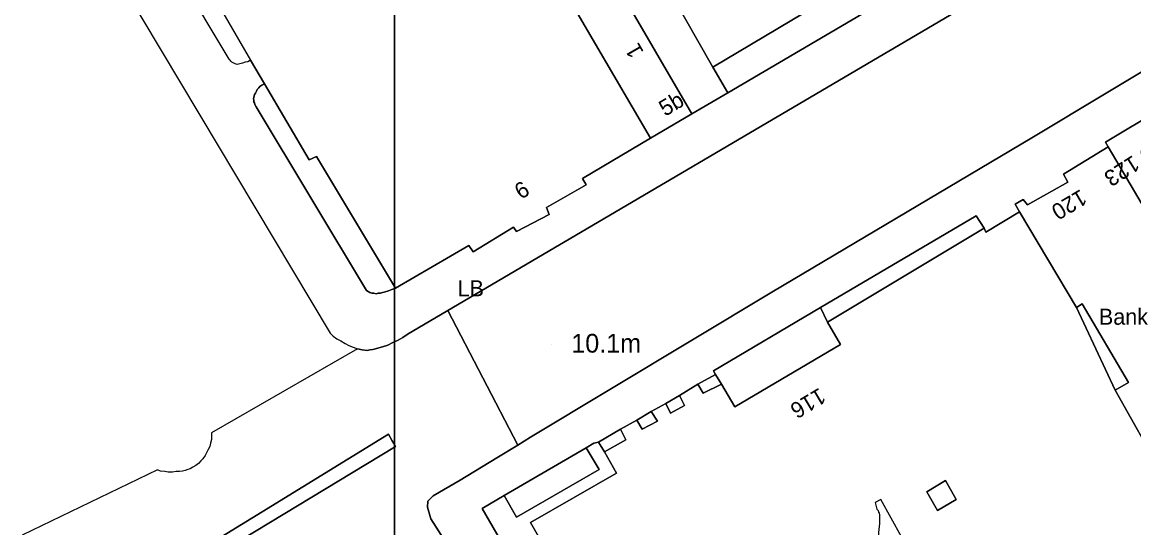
# Model space of a CAD drawing. Extents: x 529240 to 530363, y 179600 to 180767.
# Drawn here: x 529681.3 to 529784.9, y 180348 to 180395.2 of the extents above; entities that cross this region are included whole.
import ezdxf

# ---------------------------------------------------------------- set-up
doc = ezdxf.new("R2010")
doc.units = 0
for name, color, linetype in [('Building', 7, 'Continuous'), ('General surface', 7, 'Continuous'), ('Road Or Track', 7, 'Continuous'), ('Roadside', 7, 'Continuous'), ('Structure', 7, 'Continuous'), ('Unclassified', 7, 'Continuous')]:
    doc.layers.add(name, color=color, linetype=linetype)

msp = doc.modelspace()

# ---------------------------------------------------------------- linework, layer by layer
at = {"layer": 'Building'}
for points in [[(529747.1, 180388.6), (529784.75, 180410.75), (529775.55, 180427), (529778.6, 180428.75), (529776, 180433.1), (529773.05, 180431.45), (529759.35, 180455.35), (529756.45, 180453.55), (529769.05, 180432.45), (529767.7, 180431.65), (529772.95, 180422.55), (529773.05, 180422.45), (529773.2, 180422.35), (529774.1, 180422.9), (529780.7, 180411.95), (529755.35, 180396.75), (529745.7, 180391)], [(529716, 180434.29), (529716.5, 180433.45), (529720.55, 180426.5), (529724.85, 180419.1), (529726.9, 180415.6), (529730.95, 180408.6), (529733, 180405.1), (529735.15, 180401.4), (529736.95, 180398.3), (529743.75, 180386.65), (529747.1, 180388.6), (529745.7, 180391), (529734.1, 180411.4), (529730.5, 180417.75), (529722.5, 180431.8), (529716, 180443.25)], [(529716, 180370.52), (529716, 180424.74), (529713.4, 180423.25), (529710.65, 180427.9), (529701.85, 180422.65), (529698.8, 180420.8), (529701.85, 180415.6), (529692.65, 180410.05), (529699.5, 180398.5), (529698.9, 180398.05), (529702.6, 180391.65), (529703.9, 180389.45), (529708.05, 180382.35), (529708.75, 180382.65)], [(529716, 180370.52), (529716.1, 180370.35), (529722.95, 180374.35), (529723.35, 180373.75), (529727.1, 180376.05), (529727.4, 180375.65), (529730.45, 180377.25), (529730.2, 180377.9), (529733.9, 180380), (529733.55, 180380.6), (529739.9, 180384.35), (529733.05, 180396.05), (529731.3, 180399.05), (529729.1, 180402.8), (529727.05, 180406.3), (529722.9, 180413.35), (529720.85, 180416.95), (529716.6, 180424.2), (529716.2, 180424.85), (529716, 180424.74)], [(529745.7, 180391), (529755.35, 180396.75), (529748.25, 180408.65), (529748, 180408.5), (529743.3, 180416.7), (529738.4, 180413.8), (529734.1, 180411.4)], [(529743.75, 180386.65), (529736.95, 180398.3), (529733.05, 180396.05), (529739.9, 180384.35)], [(529779.6, 180368.55), (529780.15, 180368.9), (529784.45, 180361.55), (529783.2, 180360.85), (529787.65, 180352.95), (529796.25, 180357.75), (529791.95, 180366.45), (529791.35, 180367.7), (529790.9, 180368.45), (529789.5, 180367.6), (529788.3, 180369.55), (529789.75, 180370.45), (529789.7, 180371.7), (529788.8, 180372.95), (529782.55, 180383.55), (529778.4, 180381), (529778.8, 180380.25), (529775.05, 180378.15), (529774.65, 180378.65), (529773.9, 180378.2), (529774.3, 180377.5)], [(529733.9, 180355.45), (529726.25, 180351), (529727.4, 180349), (529735.1, 180353.45)], [(529766.65, 180349.6), (529768.4, 180350.65), (529767.4, 180352.4), (529765.65, 180351.35)], [(529761, 180349.75), (529761.1, 180349.6), (529761.15, 180349.45), (529761.2, 180349.35), (529761.25, 180349.2), (529761.25, 180348.4), (529761.15, 180347.55), (529761.15, 180347.05), (529761.2, 180346.9), (529761.4, 180346.1), (529763.3, 180347.15), (529761.35, 180350.65), (529760.85, 180350.35)]]:
    msp.add_lwpolyline(points, close=True, dxfattribs=at)
for points in [[(529747.1, 180388.6), (529784.75, 180410.75), (529775.55, 180427), (529778.6, 180428.75), (529776, 180433.1), (529773.05, 180431.45), (529759.35, 180455.35)], [(529734.1, 180411.4), (529745.7, 180391)], [(529743.75, 180386.65), (529736.95, 180398.3)], [(529745.7, 180391), (529755.35, 180396.75)], [(529739.9, 180384.35), (529733.05, 180396.05)], [(529796, 180392.15), (529791.25, 180389.3), (529790.8, 180389.75), (529787.25, 180387.65), (529787.5, 180387.1), (529782.3, 180384), (529782.55, 180383.55)], [(529745.7, 180391), (529747.1, 180388.6)], [(529703.9, 180389.45), (529708.05, 180382.35), (529708.75, 180382.65), (529716, 180370.52)], [(529743.75, 180386.65), (529747.1, 180388.6)], [(529739.9, 180384.35), (529743.75, 180386.65)], [(529787.5, 180387.1), (529782.3, 180384), (529782.55, 180383.55), (529788.8, 180372.95)], [(529716.1, 180370.35), (529722.95, 180374.35), (529723.35, 180373.75), (529727.1, 180376.05), (529727.4, 180375.65), (529730.45, 180377.25), (529730.2, 180377.9), (529733.9, 180380), (529733.55, 180380.6), (529739.9, 180384.35)], [(529782.55, 180383.55), (529778.4, 180381), (529778.8, 180380.25), (529775.05, 180378.15), (529774.65, 180378.65), (529773.9, 180378.2), (529774.3, 180377.5)], [(529782.55, 180383.55), (529788.8, 180372.95)], [(529787.65, 180352.95), (529783.2, 180360.85), (529779.6, 180368.55), (529774.3, 180377.5), (529771.15, 180375.6), (529771, 180375.95), (529756.4, 180367.2), (529757.6, 180365.1), (529747.75, 180359.3), (529746.5, 180361.4), (529744.8, 180360.55), (529744.3, 180361.4), (529742.6, 180360.35), (529743.05, 180359.4), (529741.75, 180358.7), (529741.3, 180359.6), (529739.95, 180358.85), (529740.55, 180357.95), (529739.1, 180357.2), (529738.6, 180358.05), (529737.1, 180357.2), (529737.6, 180356.2), (529735.6, 180355.1), (529736.7, 180353.1), (529728.7, 180348.5), (529732.85, 180341.2)], [(529774.3, 180377.5), (529771.15, 180375.6), (529771, 180375.95)], [(529774.3, 180377.5), (529779.6, 180368.55)], [(529771, 180375.95), (529756.4, 180367.2)], [(529716, 180370.52), (529716.1, 180370.35)], [(529783.2, 180360.85), (529784.45, 180361.55), (529780.15, 180368.9), (529779.6, 180368.55)], [(529779.6, 180368.55), (529783.2, 180360.85)], [(529756.4, 180367.2), (529757.6, 180365.1), (529747.75, 180359.3), (529746.5, 180361.4)], [(529744.3, 180361.4), (529742.6, 180360.35)], [(529746.5, 180361.4), (529744.8, 180360.55), (529744.3, 180361.4)], [(529783.2, 180360.85), (529787.65, 180352.95)], [(529741.3, 180359.6), (529739.95, 180358.85)], [(529742.6, 180360.35), (529743.05, 180359.4), (529741.75, 180358.7), (529741.3, 180359.6)], [(529739.95, 180358.85), (529740.55, 180357.95), (529739.1, 180357.2), (529738.6, 180358.05)], [(529738.6, 180358.05), (529737.1, 180357.2)], [(529737.1, 180357.2), (529737.6, 180356.2), (529735.6, 180355.1)], [(529735.6, 180355.1), (529736.7, 180353.1), (529728.7, 180348.5), (529732.85, 180341.2)], [(529768.4, 180350.65), (529766.65, 180349.6), (529765.65, 180351.35), (529767.4, 180352.4), (529768.4, 180350.65)], [(529760.85, 180350.35), (529761, 180349.75), (529761.1, 180349.6), (529761.15, 180349.45), (529761.2, 180349.35), (529761.25, 180349.2), (529761.25, 180348.4), (529761.15, 180347.55), (529761.15, 180347.05), (529761.2, 180346.9), (529761.4, 180346.1), (529763.3, 180347.15), (529761.35, 180350.65), (529760.85, 180350.35)]]:
    msp.add_lwpolyline(points, dxfattribs=at)
at = {"layer": 'General surface'}
for points in [[(529716, 180370.32), (529716, 180370.52), (529708.75, 180382.65), (529708.05, 180382.35), (529703.9, 180389.45), (529703.65, 180389.3), (529703.45, 180389.2), (529703.35, 180389.05), (529703.2, 180388.9), (529703.15, 180388.75), (529703.05, 180388.55), (529702.95, 180388.45), (529702.85, 180388.05), (529702.9, 180387.9), (529702.9, 180387.75), (529702.95, 180387.65), (529703, 180387.5), (529703.1, 180387.3), (529713.4, 180370.15), (529713.7, 180369.95), (529713.9, 180369.9), (529714.1, 180369.9), (529714.3, 180369.85), (529714.5, 180369.9), (529714.7, 180369.9), (529714.9, 180369.95), (529715.05, 180370), (529715.45, 180370.1), (529715.75, 180370.25)], [(529756.4, 180367.2), (529771, 180375.95), (529770.25, 180377.1), (529755.75, 180368.55)], [(529716, 180370.32), (529716.1, 180370.35), (529716, 180370.52)], [(529783.2, 180360.85), (529784.45, 180361.55), (529780.15, 180368.9), (529779.6, 180368.55)], [(529755.75, 180368.55), (529745.75, 180362.65), (529745.95, 180362.3), (529746.5, 180361.4), (529747.75, 180359.3), (529757.6, 180365.1), (529756.4, 180367.2)], [(529744.3, 180361.4), (529744.8, 180360.55), (529746.5, 180361.4), (529745.95, 180362.3)], [(529742.6, 180360.35), (529741.3, 180359.6), (529741.75, 180358.7), (529743.05, 180359.4)], [(529739.95, 180358.85), (529738.6, 180358.05), (529739.1, 180357.2), (529740.55, 180357.95)], [(529735.6, 180355.1), (529737.6, 180356.2), (529737.1, 180357.2), (529735.05, 180356)], [(529735.6, 180355.1), (529735.05, 180356), (529734.6, 180355.9), (529733.9, 180355.45), (529735.1, 180353.45), (529727.4, 180349), (529726.25, 180351), (529724.2, 180349.8), (529730.1, 180339.6), (529732.85, 180341.2), (529728.7, 180348.5), (529736.7, 180353.1)], [(529768.4, 180350.65), (529767.4, 180352.4), (529765.65, 180351.35), (529766.65, 180349.6)], [(529760.85, 180350.35), (529761, 180349.75), (529761.1, 180349.6), (529761.15, 180349.45), (529761.2, 180349.35), (529761.25, 180349.2), (529761.25, 180348.4), (529761.15, 180347.55), (529761.15, 180347.05), (529761.2, 180346.9), (529761.4, 180346.1), (529763.3, 180347.15), (529761.35, 180350.65)]]:
    msp.add_lwpolyline(points, close=True, dxfattribs=at)
at = {"layer": 'Road Or Track'}
for points in [[(529727.5, 180355.72), (529728.7, 180356.45), (529751.2, 180370), (529775.45, 180384.4), (529789.45, 180392.82), (529792.9, 180394.9), (529798.75, 180398.49), (529789.7, 180411.3), (529789.75, 180411), (529789.75, 180410.85), (529789.8, 180410.6), (529789.8, 180410.15), (529789.7, 180409.75), (529789.59, 180409.57), (529789.4, 180409.25), (529789, 180408.8), (529788.55, 180408.4), (529788.5, 180408.3), (529788.05, 180407.9), (529787.6, 180407.55), (529785.1, 180406.05), (529782.42, 180404.47), (529720.99, 180368.28)], [(529716, 180343.65), (529720.6, 180346.95), (529719.41, 180348.83), (529719.09, 180349.92), (529719.13, 180350.48), (529719.62, 180350.98), (529722.15, 180352.45), (529725.56, 180354.54), (529727.5, 180355.72), (529720.99, 180368.28), (529718.18, 180366.62), (529717.3, 180366.1), (529716.8, 180365.75), (529716.35, 180365.5), (529716, 180365.36), (529716, 180355.77), (529716.1, 180355.6), (529716, 180355.54)]]:
    msp.add_lwpolyline(points, close=True, dxfattribs=at)
for points in [[(529789.7, 180411.3), (529789.75, 180411), (529789.75, 180410.85), (529789.8, 180410.6), (529789.8, 180410.15), (529789.7, 180409.75), (529789.59, 180409.57), (529789.4, 180409.25), (529789, 180408.8), (529788.55, 180408.4), (529788.5, 180408.3), (529788.05, 180407.9), (529787.6, 180407.55), (529785.1, 180406.05), (529782.42, 180404.47), (529720.99, 180368.28)], [(529727.5, 180355.72), (529728.7, 180356.45), (529751.2, 180370), (529775.45, 180384.4), (529789.45, 180392.82), (529792.9, 180394.9), (529798.75, 180398.49)], [(529720.99, 180368.28), (529718.18, 180366.62), (529717.3, 180366.1), (529716.8, 180365.75), (529716.35, 180365.5), (529716, 180365.36)], [(529698.46, 180346.29), (529703.66, 180349.5), (529715.45, 180356.75), (529715.81, 180356.11), (529715.94, 180355.88), (529716, 180355.77), (529716, 180365.36), (529715.85, 180365.3), (529715.4, 180365.05), (529714.9, 180364.9), (529714.55, 180364.8), (529714.25, 180364.7), (529714, 180364.65), (529713.7, 180364.6), (529713.45, 180364.55), (529713, 180364.6), (529712.55, 180364.7), (529698.95, 180356.85), (529698.95, 180356.25), (529698.85, 180355.9), (529698.8, 180355.6), (529698.65, 180355.3), (529698.35, 180354.75), (529698.15, 180354.45), (529697.95, 180354.25), (529697.75, 180354), (529697.5, 180353.8), (529697.2, 180353.65), (529696.95, 180353.5), (529696.75, 180353.45), (529696.5, 180353.35), (529696.25, 180353.3), (529695.95, 180353.25), (529695.65, 180353.25), (529695.3, 180353.2), (529694.9, 180353.2), (529694.6, 180353.25), (529694.2, 180353.3), (529693.9, 180353.4), (529681.3, 180347.3)], [(529716, 180365.36), (529715.85, 180365.3), (529715.4, 180365.05), (529714.9, 180364.9), (529714.55, 180364.8), (529714.25, 180364.7), (529714, 180364.65), (529713.7, 180364.6), (529713.45, 180364.55), (529713, 180364.6), (529712.55, 180364.7)], [(529716, 180355.54), (529701.78, 180346.9), (529700.87, 180346.35), (529683.6, 180335.85), (529682.95, 180336.75), (529686.63, 180339.02), (529698.46, 180346.29), (529703.66, 180349.5), (529715.45, 180356.75), (529715.81, 180356.11), (529715.94, 180355.88), (529716, 180355.77)], [(529716, 180343.65), (529716, 180355.54), (529701.78, 180346.9)], [(529716, 180355.77), (529716.1, 180355.6)], [(529716.1, 180355.6), (529716, 180355.54)], [(529727.5, 180355.72), (529725.56, 180354.54), (529722.15, 180352.45)], [(529720.6, 180346.95), (529719.41, 180348.83), (529719.09, 180349.92), (529719.13, 180350.48), (529719.62, 180350.98), (529722.15, 180352.45)]]:
    msp.add_lwpolyline(points, dxfattribs=at)
at = {"layer": 'Roadside'}
for points in [[(529784.75, 180410.75), (529747.1, 180388.6), (529743.75, 180386.65), (529739.9, 180384.35), (529733.55, 180380.6), (529733.9, 180380), (529730.2, 180377.9), (529730.45, 180377.25), (529727.4, 180375.65), (529727.1, 180376.05), (529723.35, 180373.75), (529722.95, 180374.35), (529716.1, 180370.35), (529716, 180370.32), (529716, 180365.36), (529716.35, 180365.5), (529716.8, 180365.75), (529717.3, 180366.1), (529718.18, 180366.62), (529720.99, 180368.28), (529782.42, 180404.47)], [(529690.75, 180398.45), (529710, 180366.15), (529710.3, 180365.9), (529710.65, 180365.65), (529711, 180365.45), (529711.4, 180365.2), (529711.75, 180365), (529712.55, 180364.7), (529713, 180364.6), (529713.45, 180364.55), (529713.7, 180364.6), (529714, 180364.65), (529714.25, 180364.7), (529714.55, 180364.8), (529714.9, 180364.9), (529715.4, 180365.05), (529715.85, 180365.3), (529716, 180365.36), (529716, 180370.32), (529715.75, 180370.25), (529715.45, 180370.1), (529715.05, 180370), (529714.9, 180369.95), (529714.7, 180369.9), (529714.5, 180369.9), (529714.3, 180369.85), (529714.1, 180369.9), (529713.9, 180369.9), (529713.7, 180369.95), (529713.4, 180370.15), (529703.1, 180387.3), (529703, 180387.5), (529702.95, 180387.65), (529702.9, 180387.75), (529702.9, 180387.9), (529702.85, 180388.05), (529702.95, 180388.45), (529703.05, 180388.55), (529703.15, 180388.75), (529703.2, 180388.9), (529703.35, 180389.05), (529703.45, 180389.2), (529703.65, 180389.3), (529703.9, 180389.45), (529702.6, 180391.65), (529702.35, 180391.5), (529702.1, 180391.45), (529701.85, 180391.35), (529701.35, 180391.25), (529701.15, 180391.3), (529700.85, 180391.45), (529700.75, 180391.55), (529700.7, 180391.65), (529700.6, 180391.75), (529691.3, 180407.3)], [(529789.45, 180392.82), (529775.45, 180384.4), (529751.2, 180370), (529728.7, 180356.45), (529727.5, 180355.72), (529725.56, 180354.54), (529722.15, 180352.45), (529719.62, 180350.98), (529719.13, 180350.48), (529719.09, 180349.92), (529719.41, 180348.83), (529720.6, 180346.95)], [(529730.1, 180339.6), (529724.2, 180349.8), (529726.25, 180351), (529733.9, 180355.45), (529734.6, 180355.9), (529735.05, 180356), (529737.1, 180357.2), (529738.6, 180358.05), (529739.95, 180358.85), (529741.3, 180359.6), (529742.6, 180360.35), (529744.3, 180361.4), (529745.95, 180362.3), (529745.75, 180362.65), (529755.75, 180368.55), (529770.25, 180377.1), (529771, 180375.95), (529771.15, 180375.6), (529774.3, 180377.5), (529773.9, 180378.2), (529774.65, 180378.65), (529775.05, 180378.15), (529778.8, 180380.25), (529778.4, 180381), (529782.55, 180383.55), (529782.3, 180384), (529787.5, 180387.1)]]:
    msp.add_lwpolyline(points, dxfattribs=at)
for points in [[(529716, 180355.54), (529716, 180355.77), (529715.94, 180355.88), (529715.81, 180356.11), (529715.45, 180356.75), (529703.66, 180349.5), (529698.46, 180346.29), (529686.63, 180339.02), (529682.95, 180336.75), (529683.6, 180335.85), (529700.87, 180346.35), (529701.78, 180346.9)], [(529716, 180355.54), (529716.1, 180355.6), (529716, 180355.77)]]:
    msp.add_lwpolyline(points, close=True, dxfattribs=at)
at = {"layer": 'Structure'}
msp.add_line((529723.55, 180370.55), (529723.55, 180370.55), dxfattribs=at)
at = {"layer": 'Unclassified'}
msp.add_line((529730.65, 180365.1), (529730.65, 180365.1), dxfattribs=at)
for points in [[(529703.9, 180389.45), (529703.65, 180389.3), (529703.45, 180389.2), (529703.35, 180389.05), (529703.2, 180388.9), (529703.15, 180388.75), (529703.05, 180388.55), (529702.95, 180388.45), (529702.85, 180388.05), (529702.9, 180387.9), (529702.9, 180387.75), (529702.95, 180387.65), (529703, 180387.5), (529703.1, 180387.3), (529713.4, 180370.15), (529713.7, 180369.95), (529713.9, 180369.9), (529714.1, 180369.9), (529714.3, 180369.85), (529714.5, 180369.9), (529714.7, 180369.9), (529714.9, 180369.95), (529715.05, 180370), (529715.45, 180370.1), (529715.75, 180370.25), (529716, 180370.32)], [(529755.75, 180368.55), (529770.25, 180377.1), (529771, 180375.95)], [(529716, 180370.32), (529716.1, 180370.35)], [(529720.99, 180368.28), (529727.5, 180355.72)], [(529745.95, 180362.3), (529745.75, 180362.65), (529755.75, 180368.55)], [(529756.4, 180367.2), (529755.75, 180368.55)], [(529745.95, 180362.3), (529744.3, 180361.4)], [(529746.5, 180361.4), (529745.95, 180362.3)], [(529742.6, 180360.35), (529741.3, 180359.6)], [(529739.95, 180358.85), (529738.6, 180358.05)], [(529737.1, 180357.2), (529735.05, 180356)], [(529726.25, 180351), (529727.4, 180349), (529735.1, 180353.45), (529733.9, 180355.45)], [(529733.9, 180355.45), (529726.25, 180351)], [(529735.05, 180356), (529734.6, 180355.9), (529733.9, 180355.45)], [(529735.05, 180356), (529735.6, 180355.1)], [(529726.25, 180351), (529724.2, 180349.8), (529730.1, 180339.6)]]:
    msp.add_lwpolyline(points, dxfattribs=at)

# ---------------------------------------------------------------- texts
at = {"layer": 'Structure'}
msp.add_text('LB', height=1.5, dxfattribs=at).set_placement((529721.9, 180369.6))
at = {"layer": 'Unclassified'}
for s, rotation, p in [('1', 120, (529739.3, 180392.4)), ('5b', 31, (529741.25, 180386.35)), ('121 to 123', 212.3, (529790.05, 180386.1)), ('6', 31.6, (529727.8, 180378.6)), ('120', 210.6, (529780, 180379.65)), ('116', 210.9, (529755.64, 180361.12))]:
    msp.add_text(s, height=1.5, rotation=rotation, dxfattribs=at).set_placement(p)
for s, height, p in [('Bank', 1.5, (529781.7, 180366.95)), ('10.1m', 1.75, (529732.5, 180364.35))]:
    msp.add_text(s, height=height, dxfattribs=at).set_placement(p)

doc.saveas('drawing.dxf')
